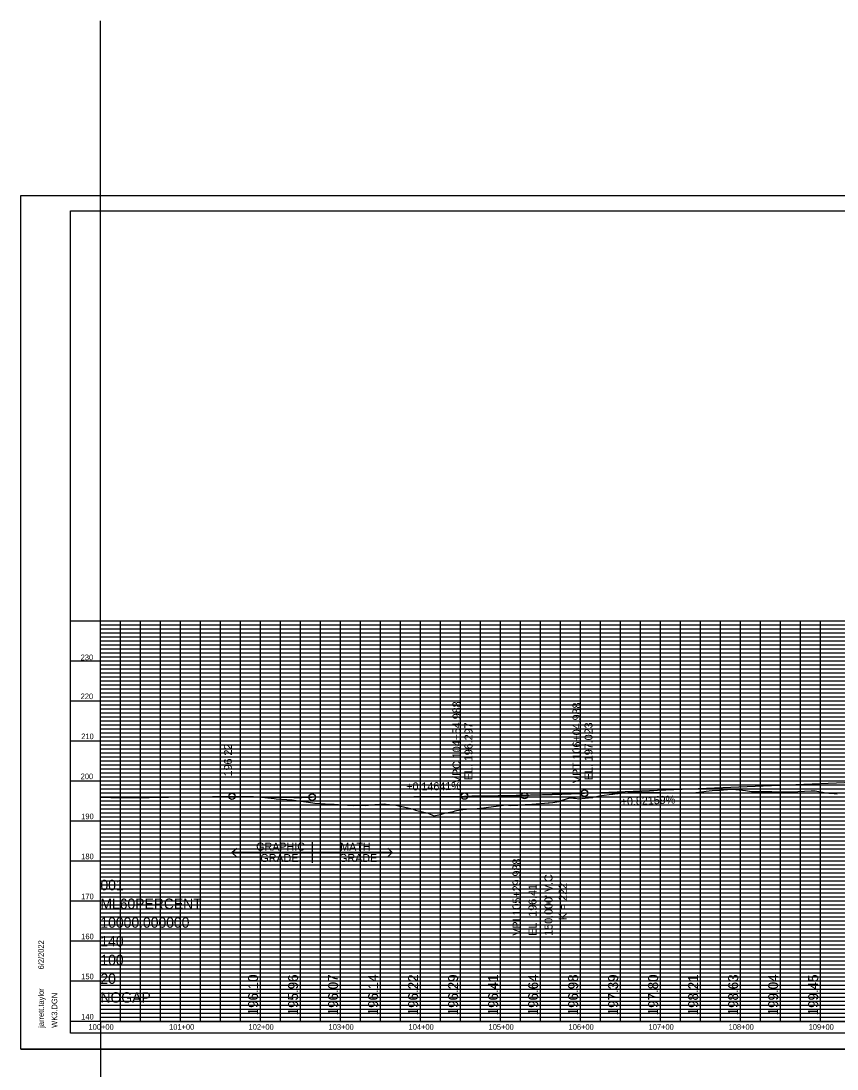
# Model space of a CAD drawing. Extents: x 1386057 to 1388056, y 1972278 to 1974778.
# Drawn here: x 1386057 to 1387077, y 1973468 to 1974778 of the extents above; entities that cross this region are included whole.
import ezdxf

# ---------------------------------------------------------------- set-up
doc = ezdxf.new("R2010")
doc.units = 0
for name, color, linetype in [('Default', 7, 'Continuous'), ('PROFILE_CELL', 7, 'Continuous'), ('PROFILES_1', 7, 'Continuous'), ('PROFILES_TX_GRADES', 7, 'Continuous'), ('PROFILES_TX_STRIP', 7, 'Continuous'), ('PROFILES_TX_VPI', 7, 'Continuous'), ('R_Border', 7, 'Continuous'), ('R_Grid', 7, 'Continuous'), ('R_No Plot', 7, 'Continuous'), ('X_PROFILES_1', 7, 'Continuous')]:
    doc.layers.add(name, color=color, linetype=linetype)

msp = doc.modelspace()

# ---------------------------------------------------------------- linework, layer by layer
at = {"layer": 'Default'}
for p, q in [((1386320.9, 1973738.7), (1386327, 1973744.4)), ((1386421.1, 1973751.6), (1386421.1, 1973738.7)), ((1386515.7, 1973744.2), (1386521.3, 1973738.7)), ((1386421.1, 1973738.7), (1386320.9, 1973738.7)), ((1386320.9, 1973738.7), (1386326.5, 1973733.3)), ((1386521.3, 1973738.7), (1386421.1, 1973738.7)), ((1386421.1, 1973738.7), (1386421.1, 1973725.8)), ((1386515.3, 1973733.1), (1386521.3, 1973738.7))]:
    msp.add_line(p, q, dxfattribs=at)
at = {"layer": 'PROFILE_CELL'}
for q in [(1386156.5, 1974777.8), (1388056.5, 1973527.8), (1386156.5, 1972277.8)]:
    msp.add_line((1386156.5, 1973527.8), q, dxfattribs=at)
at = {"layer": 'PROFILES_1'}
for p, q in [((1386761.5, 1973812.9), (1387342.2, 1973836.8)), ((1386320.9, 1973808.9), (1386327, 1973808.9)), ((1386327, 1973808.9), (1386327.2, 1973808.9)), ((1386327.2, 1973808.9), (1386334.9, 1973808.8)), ((1386334.9, 1973808.8), (1386337.4, 1973808.8)), ((1386337.4, 1973808.8), (1386342, 1973808.7)), ((1386342, 1973808.7), (1386343.1, 1973808.7)), ((1386343.1, 1973808.7), (1386347.6, 1973808.6)), ((1386347.6, 1973808.6), (1386357.2, 1973808.3)), ((1386357.2, 1973808.3), (1386357.7, 1973808.3)), ((1386357.7, 1973808.3), (1386367.8, 1973808.1)), ((1386367.8, 1973808.1), (1386372.6, 1973808.1)), ((1386372.6, 1973808.1), (1386377.9, 1973808)), ((1386377.9, 1973808), (1386388, 1973808)), ((1386388, 1973808), (1386398.1, 1973807.7)), ((1386398.1, 1973807.7), (1386402.8, 1973807.6)), ((1386402.8, 1973807.6), (1386408.2, 1973807.7)), ((1386408.2, 1973807.7), (1386418, 1973807.9)), ((1386418, 1973807.9), (1386418.3, 1973807.9)), ((1386418.3, 1973807.9), (1386421.1, 1973807.9)), ((1386421.1, 1973807.9), (1386611.5, 1973809.3))]:
    msp.add_line(p, q, dxfattribs=at)
msp.add_spline([(1386611.5, 1973809.3), (1386614.5, 1973809.3), (1386617.5, 1973809.3), (1386620.5, 1973809.4), (1386623.5, 1973809.4), (1386626.5, 1973809.4), (1386629.5, 1973809.5), (1386632.5, 1973809.5), (1386635.5, 1973809.5), (1386638.5, 1973809.6), (1386641.5, 1973809.6), (1386644.5, 1973809.7), (1386647.5, 1973809.7), (1386650.5, 1973809.7), (1386653.5, 1973809.8), (1386656.5, 1973809.8), (1386659.5, 1973809.9), (1386662.5, 1973810), (1386665.5, 1973810), (1386668.5, 1973810.1), (1386671.5, 1973810.1), (1386674.5, 1973810.2), (1386677.5, 1973810.3), (1386680.5, 1973810.3), (1386683.5, 1973810.4), (1386686.5, 1973810.5), (1386689.5, 1973810.5), (1386692.5, 1973810.6), (1386695.5, 1973810.7), (1386698.5, 1973810.8), (1386701.5, 1973810.9), (1386704.5, 1973810.9), (1386707.5, 1973811), (1386710.5, 1973811.1), (1386713.5, 1973811.2), (1386716.5, 1973811.3), (1386719.5, 1973811.4), (1386722.5, 1973811.5), (1386725.5, 1973811.6), (1386728.5, 1973811.7), (1386731.5, 1973811.8), (1386734.5, 1973811.9), (1386737.5, 1973812), (1386740.5, 1973812.1), (1386743.5, 1973812.2), (1386746.5, 1973812.3), (1386749.5, 1973812.4), (1386752.5, 1973812.6), (1386755.5, 1973812.7), (1386758.5, 1973812.8), (1386761.5, 1973812.9)], degree=3, dxfattribs=at)
at = {"layer": 'PROFILES_TX_GRADES'}
for p, q in [((1386611.5, 1973809.3), (1386682.5, 1973809.8)), ((1386761.5, 1973812.9), (1386690.5, 1973810))]:
    msp.add_line(p, q, dxfattribs=at)
for centre in [(1386320.9, 1973808.9), (1386421.1, 1973807.9), (1386611.5, 1973809.3), (1386686.5, 1973809.8), (1386761.5, 1973812.9)]:
    msp.add_circle(centre, 4, dxfattribs=at)
at = {"layer": 'R_Border'}
for p, q in [((1386119.2, 1974540.4), (1387700.1, 1974540.4)), ((1386119.2, 1973513.1), (1386119.2, 1974540.4)), ((1387700.1, 1974027.8), (1386119.2, 1974027.8)), ((1386156.5, 1973527.8), (1386156.5, 1974027.8)), ((1386206.5, 1973527.8), (1386206.5, 1974027.8)), ((1386256.5, 1973527.8), (1386256.5, 1974027.8)), ((1386306.5, 1973527.8), (1386306.5, 1974027.8)), ((1386356.5, 1973527.8), (1386356.5, 1974027.8)), ((1386406.5, 1973527.8), (1386406.5, 1974027.8)), ((1386456.5, 1973527.8), (1386456.5, 1974027.8)), ((1386506.5, 1973527.8), (1386506.5, 1974027.8)), ((1386556.5, 1973527.8), (1386556.5, 1974027.8)), ((1386606.5, 1973527.8), (1386606.5, 1974027.8)), ((1386656.5, 1973527.8), (1386656.5, 1974027.8)), ((1386706.5, 1973527.8), (1386706.5, 1974027.8)), ((1386756.5, 1973527.8), (1386756.5, 1974027.8)), ((1386806.5, 1973527.8), (1386806.5, 1974027.8)), ((1386856.5, 1973527.8), (1386856.5, 1974027.8)), ((1386906.5, 1973527.8), (1386906.5, 1974027.8)), ((1386956.5, 1973527.8), (1386956.5, 1974027.8)), ((1387006.5, 1973527.8), (1387006.5, 1974027.8)), ((1387056.5, 1973527.8), (1387056.5, 1974027.8)), ((1387700.1, 1973977.8), (1386119.2, 1973977.8)), ((1387700.1, 1973927.8), (1386119.2, 1973927.8)), ((1387700.1, 1973877.8), (1386119.2, 1973877.8)), ((1387700.1, 1973827.8), (1386119.2, 1973827.8)), ((1387700.1, 1973777.8), (1386119.2, 1973777.8)), ((1387700.1, 1973727.8), (1386119.2, 1973727.8)), ((1387700.1, 1973677.8), (1386119.2, 1973677.8)), ((1387700.1, 1973627.8), (1386119.2, 1973627.8)), ((1387700.1, 1973577.8), (1386119.2, 1973577.8)), ((1387700.1, 1973527.8), (1386119.2, 1973527.8)), ((1386119.2, 1973513.1), (1386119.2, 1973513.1)), ((1387700.1, 1973513.1), (1386119.2, 1973513.1))]:
    msp.add_line(p, q, dxfattribs=at)
at = {"layer": 'R_Grid'}
for p, q in [((1387656.5, 1974022.8), (1386156.5, 1974022.8)), ((1387656.5, 1974017.8), (1386156.5, 1974017.8)), ((1386181.5, 1973527.8), (1386181.5, 1974027.8)), ((1386231.5, 1973527.8), (1386231.5, 1974027.8)), ((1386281.5, 1973527.8), (1386281.5, 1974027.8)), ((1386331.5, 1973527.8), (1386331.5, 1974027.8)), ((1386381.5, 1973527.8), (1386381.5, 1974027.8)), ((1386431.5, 1973527.8), (1386431.5, 1974027.8)), ((1386481.5, 1973527.8), (1386481.5, 1974027.8)), ((1386531.5, 1973527.8), (1386531.5, 1974027.8)), ((1386581.5, 1973527.8), (1386581.5, 1974027.8)), ((1386631.5, 1973527.8), (1386631.5, 1974027.8)), ((1386681.5, 1973527.8), (1386681.5, 1974027.8)), ((1386731.5, 1973527.8), (1386731.5, 1974027.8)), ((1386781.5, 1973527.8), (1386781.5, 1974027.8)), ((1386831.5, 1973527.8), (1386831.5, 1974027.8)), ((1386881.5, 1973527.8), (1386881.5, 1974027.8)), ((1386931.5, 1973527.8), (1386931.5, 1974027.8)), ((1386981.5, 1973527.8), (1386981.5, 1974027.8)), ((1387031.5, 1973527.8), (1387031.5, 1974027.8)), ((1387656.5, 1974012.8), (1386156.5, 1974012.8)), ((1387656.5, 1974007.8), (1386156.5, 1974007.8)), ((1387656.5, 1974002.8), (1386156.5, 1974002.8)), ((1387656.5, 1973997.8), (1386156.5, 1973997.8)), ((1387656.5, 1973992.8), (1386156.5, 1973992.8)), ((1387656.5, 1973987.8), (1386156.5, 1973987.8)), ((1387656.5, 1973982.8), (1386156.5, 1973982.8)), ((1387656.5, 1973972.8), (1386156.5, 1973972.8)), ((1387656.5, 1973967.8), (1386156.5, 1973967.8)), ((1387656.5, 1973962.8), (1386156.5, 1973962.8)), ((1387656.5, 1973957.8), (1386156.5, 1973957.8)), ((1387656.5, 1973952.8), (1386156.5, 1973952.8)), ((1387656.5, 1973947.8), (1386156.5, 1973947.8)), ((1387656.5, 1973942.8), (1386156.5, 1973942.8)), ((1387656.5, 1973937.8), (1386156.5, 1973937.8)), ((1387656.5, 1973932.8), (1386156.5, 1973932.8)), ((1387656.5, 1973922.8), (1386156.5, 1973922.8)), ((1387656.5, 1973917.8), (1386156.5, 1973917.8)), ((1387656.5, 1973912.8), (1386156.5, 1973912.8)), ((1387656.5, 1973907.8), (1386156.5, 1973907.8)), ((1387656.5, 1973902.8), (1386156.5, 1973902.8)), ((1387656.5, 1973897.8), (1386156.5, 1973897.8)), ((1387656.5, 1973892.8), (1386156.5, 1973892.8)), ((1387656.5, 1973887.8), (1386156.5, 1973887.8)), ((1387656.5, 1973882.8), (1386156.5, 1973882.8)), ((1387656.5, 1973872.8), (1386156.5, 1973872.8)), ((1387656.5, 1973867.8), (1386156.5, 1973867.8)), ((1387656.5, 1973862.8), (1386156.5, 1973862.8)), ((1387656.5, 1973857.8), (1386156.5, 1973857.8)), ((1387656.5, 1973852.8), (1386156.5, 1973852.8)), ((1387656.5, 1973847.8), (1386156.5, 1973847.8)), ((1387656.5, 1973842.8), (1386156.5, 1973842.8)), ((1387656.5, 1973837.8), (1386156.5, 1973837.8)), ((1387656.5, 1973832.8), (1386156.5, 1973832.8)), ((1387656.5, 1973822.8), (1386156.5, 1973822.8)), ((1387656.5, 1973817.8), (1386156.5, 1973817.8)), ((1387656.5, 1973812.8), (1386156.5, 1973812.8)), ((1387656.5, 1973807.8), (1386156.5, 1973807.8)), ((1387656.5, 1973802.8), (1386156.5, 1973802.8)), ((1387656.5, 1973797.8), (1386156.5, 1973797.8)), ((1387656.5, 1973792.8), (1386156.5, 1973792.8)), ((1387656.5, 1973787.8), (1386156.5, 1973787.8)), ((1387656.5, 1973782.8), (1386156.5, 1973782.8)), ((1387656.5, 1973772.8), (1386156.5, 1973772.8)), ((1387656.5, 1973767.8), (1386156.5, 1973767.8)), ((1387656.5, 1973762.8), (1386156.5, 1973762.8)), ((1387656.5, 1973757.8), (1386156.5, 1973757.8)), ((1387656.5, 1973752.8), (1386156.5, 1973752.8)), ((1387656.5, 1973747.8), (1386156.5, 1973747.8)), ((1387656.5, 1973742.8), (1386156.5, 1973742.8)), ((1387656.5, 1973737.8), (1386156.5, 1973737.8)), ((1387656.5, 1973732.8), (1386156.5, 1973732.8)), ((1387656.5, 1973722.8), (1386156.5, 1973722.8)), ((1387656.5, 1973717.8), (1386156.5, 1973717.8)), ((1387656.5, 1973712.8), (1386156.5, 1973712.8)), ((1387656.5, 1973707.8), (1386156.5, 1973707.8)), ((1387656.5, 1973702.8), (1386156.5, 1973702.8)), ((1387656.5, 1973697.8), (1386156.5, 1973697.8)), ((1387656.5, 1973692.8), (1386156.5, 1973692.8)), ((1387656.5, 1973687.8), (1386156.5, 1973687.8)), ((1387656.5, 1973682.8), (1386156.5, 1973682.8)), ((1387656.5, 1973672.8), (1386156.5, 1973672.8)), ((1387656.5, 1973667.8), (1386156.5, 1973667.8)), ((1387656.5, 1973662.8), (1386156.5, 1973662.8)), ((1387656.5, 1973657.8), (1386156.5, 1973657.8)), ((1387656.5, 1973652.8), (1386156.5, 1973652.8)), ((1387656.5, 1973647.8), (1386156.5, 1973647.8)), ((1387656.5, 1973642.8), (1386156.5, 1973642.8)), ((1387656.5, 1973637.8), (1386156.5, 1973637.8)), ((1387656.5, 1973632.8), (1386156.5, 1973632.8)), ((1387656.5, 1973622.8), (1386156.5, 1973622.8)), ((1387656.5, 1973617.8), (1386156.5, 1973617.8)), ((1387656.5, 1973612.8), (1386156.5, 1973612.8)), ((1387656.5, 1973607.8), (1386156.5, 1973607.8)), ((1387656.5, 1973602.8), (1386156.5, 1973602.8)), ((1387656.5, 1973597.8), (1386156.5, 1973597.8)), ((1387656.5, 1973592.8), (1386156.5, 1973592.8)), ((1387656.5, 1973587.8), (1386156.5, 1973587.8)), ((1387656.5, 1973582.8), (1386156.5, 1973582.8)), ((1387656.5, 1973572.8), (1386156.5, 1973572.8)), ((1387656.5, 1973567.8), (1386156.5, 1973567.8)), ((1387656.5, 1973562.8), (1386156.5, 1973562.8)), ((1387656.5, 1973557.8), (1386156.5, 1973557.8)), ((1387656.5, 1973552.8), (1386156.5, 1973552.8)), ((1387656.5, 1973547.8), (1386156.5, 1973547.8)), ((1387656.5, 1973542.8), (1386156.5, 1973542.8)), ((1387656.5, 1973537.8), (1386156.5, 1973537.8)), ((1387656.5, 1973532.8), (1386156.5, 1973532.8))]:
    msp.add_line(p, q, dxfattribs=at)
at = {"layer": 'R_No Plot'}
for p, q in [((1386057.2, 1974559.9), (1387723.9, 1974559.9)), ((1386057.2, 1973493.2), (1387723.8, 1973493.2))]:
    msp.add_line(p, q, dxfattribs=at)
msp.add_lwpolyline([(1386057.2, 1974559.9), (1387723.9, 1974559.9), (1387723.9, 1973493.2), (1386057.2, 1973493.2)], close=True, dxfattribs=at)
at = {"layer": 'X_PROFILES_1'}
for points in [[(1386156.5, 1973807.9), (1386159.5, 1973807.8), (1386161.1, 1973807.8), (1386169.5, 1973807.6), (1386176.1, 1973807.4), (1386184.4, 1973807.3), (1386191.1, 1973807.3), (1386198.4, 1973807.4), (1386206.1, 1973807.5), (1386208.1, 1973807.5), (1386211.5, 1973807.6), (1386217.6, 1973807.7), (1386221.2, 1973807.8), (1386226, 1973807.8), (1386231.2, 1973807.8), (1386233.8, 1973807.9), (1386236.2, 1973807.8), (1386241.4, 1973808), (1386246.8, 1973808.2), (1386249.1, 1973808.3), (1386251.3, 1973808.4), (1386256, 1973808.4), (1386259.6, 1973808.4), (1386266.3, 1973808.3), (1386269.2, 1973808.4), (1386271.3, 1973808.4), (1386281.5, 1973808.5), (1386281.8, 1973808.5), (1386296.5, 1973808.8), (1386304, 1973808.8), (1386305.7, 1973808.8), (1386311.8, 1973808.8), (1386320.9, 1973808.9), (1386326.5, 1973808.9), (1386334.6, 1973808.9), (1386348.1, 1973808.5), (1386349, 1973808.4), (1386350.9, 1973808.4), (1386354, 1973808.4), (1386373.7, 1973806.4), (1386376.3, 1973806), (1386396.2, 1973804.4), (1386401.3, 1973803.7), (1386416.4, 1973801.5), (1386424.4, 1973800.5), (1386437.2, 1973799.7), (1386448.5, 1973799), (1386465.2, 1973798), (1386472.2, 1973797.5), (1386483.5, 1973798.1), (1386487.6, 1973797.6), (1386499.5, 1973798.6), (1386511.3, 1973799.5), (1386513.2, 1973799.3), (1386513.5, 1973799.3), (1386525.7, 1973798), (1386527.6, 1973797.7), (1386545.9, 1973793.5), (1386550.4, 1973791.7), (1386566, 1973788), (1386573.2, 1973784.6), (1386581.7, 1973786.4), (1386586.4, 1973788.1), (1386597.9, 1973790.2), (1386600, 1973790.9), (1386601.4, 1973791.4), (1386612.5, 1973792.8), (1386613.8, 1973792.9), (1386614, 1973792.9), (1386627.4, 1973793.6), (1386629.6, 1973793.7), (1386647.8, 1973796.1), (1386663.6, 1973798.3), (1386668.9, 1973797.6), (1386678.1, 1973798), (1386687.3, 1973798.8), (1386695.7, 1973799.3), (1386701, 1973799.6), (1386702.1, 1973799.7), (1386716.1, 1973800.9), (1386717.4, 1973801), (1386721.7, 1973801.1), (1386729.5, 1973802.7), (1386733.7, 1973804.1), (1386743.1, 1973807.1), (1386747.7, 1973806.7), (1386750.1, 1973806.5), (1386754.1, 1973806), (1386766.5, 1973807.2), (1386770.5, 1973807.4), (1386771.9, 1973807.7), (1386772.4, 1973807.8), (1386780.4, 1973809.5), (1386782.8, 1973809.9), (1386795.8, 1973811.8), (1386796.7, 1973811.8), (1386797.9, 1973811.9), (1386799.2, 1973812), (1386815.6, 1973813.7), (1386821.8, 1973814.4), (1386831.9, 1973814.2)], [(1386831.9, 1973814.2), (1386844.8, 1973814), (1386846.8, 1973814), (1386846.9, 1973814), (1386848.3, 1973814), (1386864.7, 1973813.4), (1386871.8, 1973813.2), (1386876.5, 1973813.3), (1386881, 1973813.3), (1386896.9, 1973813.4), (1386897.4, 1973813.4), (1386907.7, 1973814.7), (1386913.7, 1973815.3), (1386921, 1973816.1), (1386930.1, 1973816.8), (1386940.4, 1973817.6), (1386946, 1973818.1), (1386946.5, 1973818.1), (1386959, 1973816.7), (1386962.8, 1973816.2), (1386970, 1973815.1), (1386971.4, 1973815), (1386973, 1973815), (1386979.2, 1973814.9), (1386995.2, 1973814.9), (1386995.6, 1973814.8), (1386999.1, 1973814.6), (1387007, 1973814.6), (1387011.9, 1973814.6), (1387021.7, 1973814.6), (1387028.3, 1973815), (1387044.7, 1973815.8), (1387045.5, 1973815.8), (1387047.2, 1973815.8), (1387047.9, 1973815.8), (1387049.7, 1973815.7), (1387061, 1973813.9), (1387066.8, 1973813), (1387073.5, 1973812.5), (1387077.4, 1973812.2)]]:
    msp.add_lwpolyline(points, dxfattribs=at)

# ---------------------------------------------------------------- texts
at = {"layer": 'Default'}
for s, p in [('230', (1386131.8, 1973979.1)), ('220', (1386131.8, 1973930.4)), ('210', (1386132.5, 1973880.4)), ('200', (1386131.8, 1973830.4)), ('190', (1386132.5, 1973780.4)), ('180', (1386132.5, 1973730.4)), ('170', (1386132.5, 1973680.4)), ('160', (1386132.5, 1973630.4)), ('150', (1386132.5, 1973580.4)), ('140', (1386132.5, 1973530.1)), ('100+00', (1386141.6, 1973517.3)), ('101+00', (1386242.3, 1973517.3)), ('102+00', (1386341.6, 1973517.3)), ('103+00', (1386441.6, 1973517.3)), ('104+00', (1386541.6, 1973517.3)), ('105+00', (1386641.6, 1973517.3)), ('106+00', (1386741.6, 1973517.3)), ('107+00', (1386841.6, 1973517.3)), ('108+00', (1386941.6, 1973517.3)), ('109+00', (1387041.6, 1973517.3))]:
    msp.add_text(s, height=7, dxfattribs=at).set_placement(p)
at = {"layer": 'PROFILE_CELL'}
for s, p in [('001', (1386156.5, 1973691.6)), ('ML60PERCENT', (1386156.5, 1973668.2)), ('10000.000000', (1386156.5, 1973644.8)), ('140', (1386156.5, 1973621.4)), ('100', (1386156.5, 1973598)), ('20', (1386156.5, 1973574.6)), ('NOGAP', (1386156.5, 1973551.2))]:
    msp.add_text(s, height=13, dxfattribs=at).set_placement(p)
at = {"layer": 'PROFILES_TX_GRADES'}
for s, rotation, p in [('+0.14641%', 0.4194, (1386538.8, 1973816.3)), ('+0.82159%', 2.3523, (1386807, 1973797.3))]:
    msp.add_text(s, height=10, rotation=rotation, dxfattribs=at).set_placement(p)
at = {"layer": 'PROFILES_TX_STRIP'}
for s, p in [('196.10', (1386353.5, 1973535.3)), ('195.96', (1386403.5, 1973535.3)), ('196.07', (1386453.5, 1973535.3)), ('196.14', (1386503.5, 1973535.3)), ('196.22', (1386553.5, 1973535.3)), ('196.29', (1386603.5, 1973535.3)), ('196.41', (1386653.5, 1973535.3)), ('196.64', (1386703.5, 1973535.3)), ('196.98', (1386753.5, 1973535.3)), ('197.39', (1386803.5, 1973535.3)), ('197.80', (1386853.5, 1973535.3)), ('198.21', (1386903.5, 1973535.3)), ('198.63', (1386953.5, 1973535.3)), ('199.04', (1387003.5, 1973535.3)), ('199.45', (1387053.5, 1973535.3))]:
    msp.add_text(s, height=12.5, rotation=90, dxfattribs=at).set_placement(p)
at = {"layer": 'PROFILES_TX_VPI'}
for s, p in [('VPC 104+54.988', (1386606.5, 1973825.4)), ('VPT 106+04.988', (1386756.5, 1973825.4)), (' EL. 196.297', (1386621.5, 1973825.4)), (' EL. 197.023', (1386771.5, 1973825.4)), ('196.22', (1386320.9, 1973833.9)), ('VPI 105+29.988', (1386681.5, 1973634.8)), ("150.000' V.C.", (1386721.5, 1973634.8)), ('EL. 196.41', (1386701.5, 1973634.8)), ('K = 222', (1386739.3, 1973654.3))]:
    msp.add_text(s, height=10, rotation=90, dxfattribs=at).set_placement(p)
for s, p in [('GRAPHIC', (1386351.2, 1973741.1)), ('MATH', (1386456.2, 1973741)), ('GRADE', (1386356.4, 1973726.9)), ('GRADE', (1386454.8, 1973726.9))]:
    msp.add_text(s, height=10, dxfattribs=at).set_placement(p)
at = {"layer": 'R_Border'}
for s, p in [('6/2/2022', (1386085.8, 1973592.7)), ('jarrett.taylor', (1386085.8, 1973519.7)), ('WK3.DGN', (1386102.5, 1973519.7))]:
    msp.add_text(s, height=7, rotation=90, dxfattribs=at).set_placement(p)

doc.saveas('drawing.dxf')
